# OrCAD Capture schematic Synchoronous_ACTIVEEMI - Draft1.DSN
size Custom
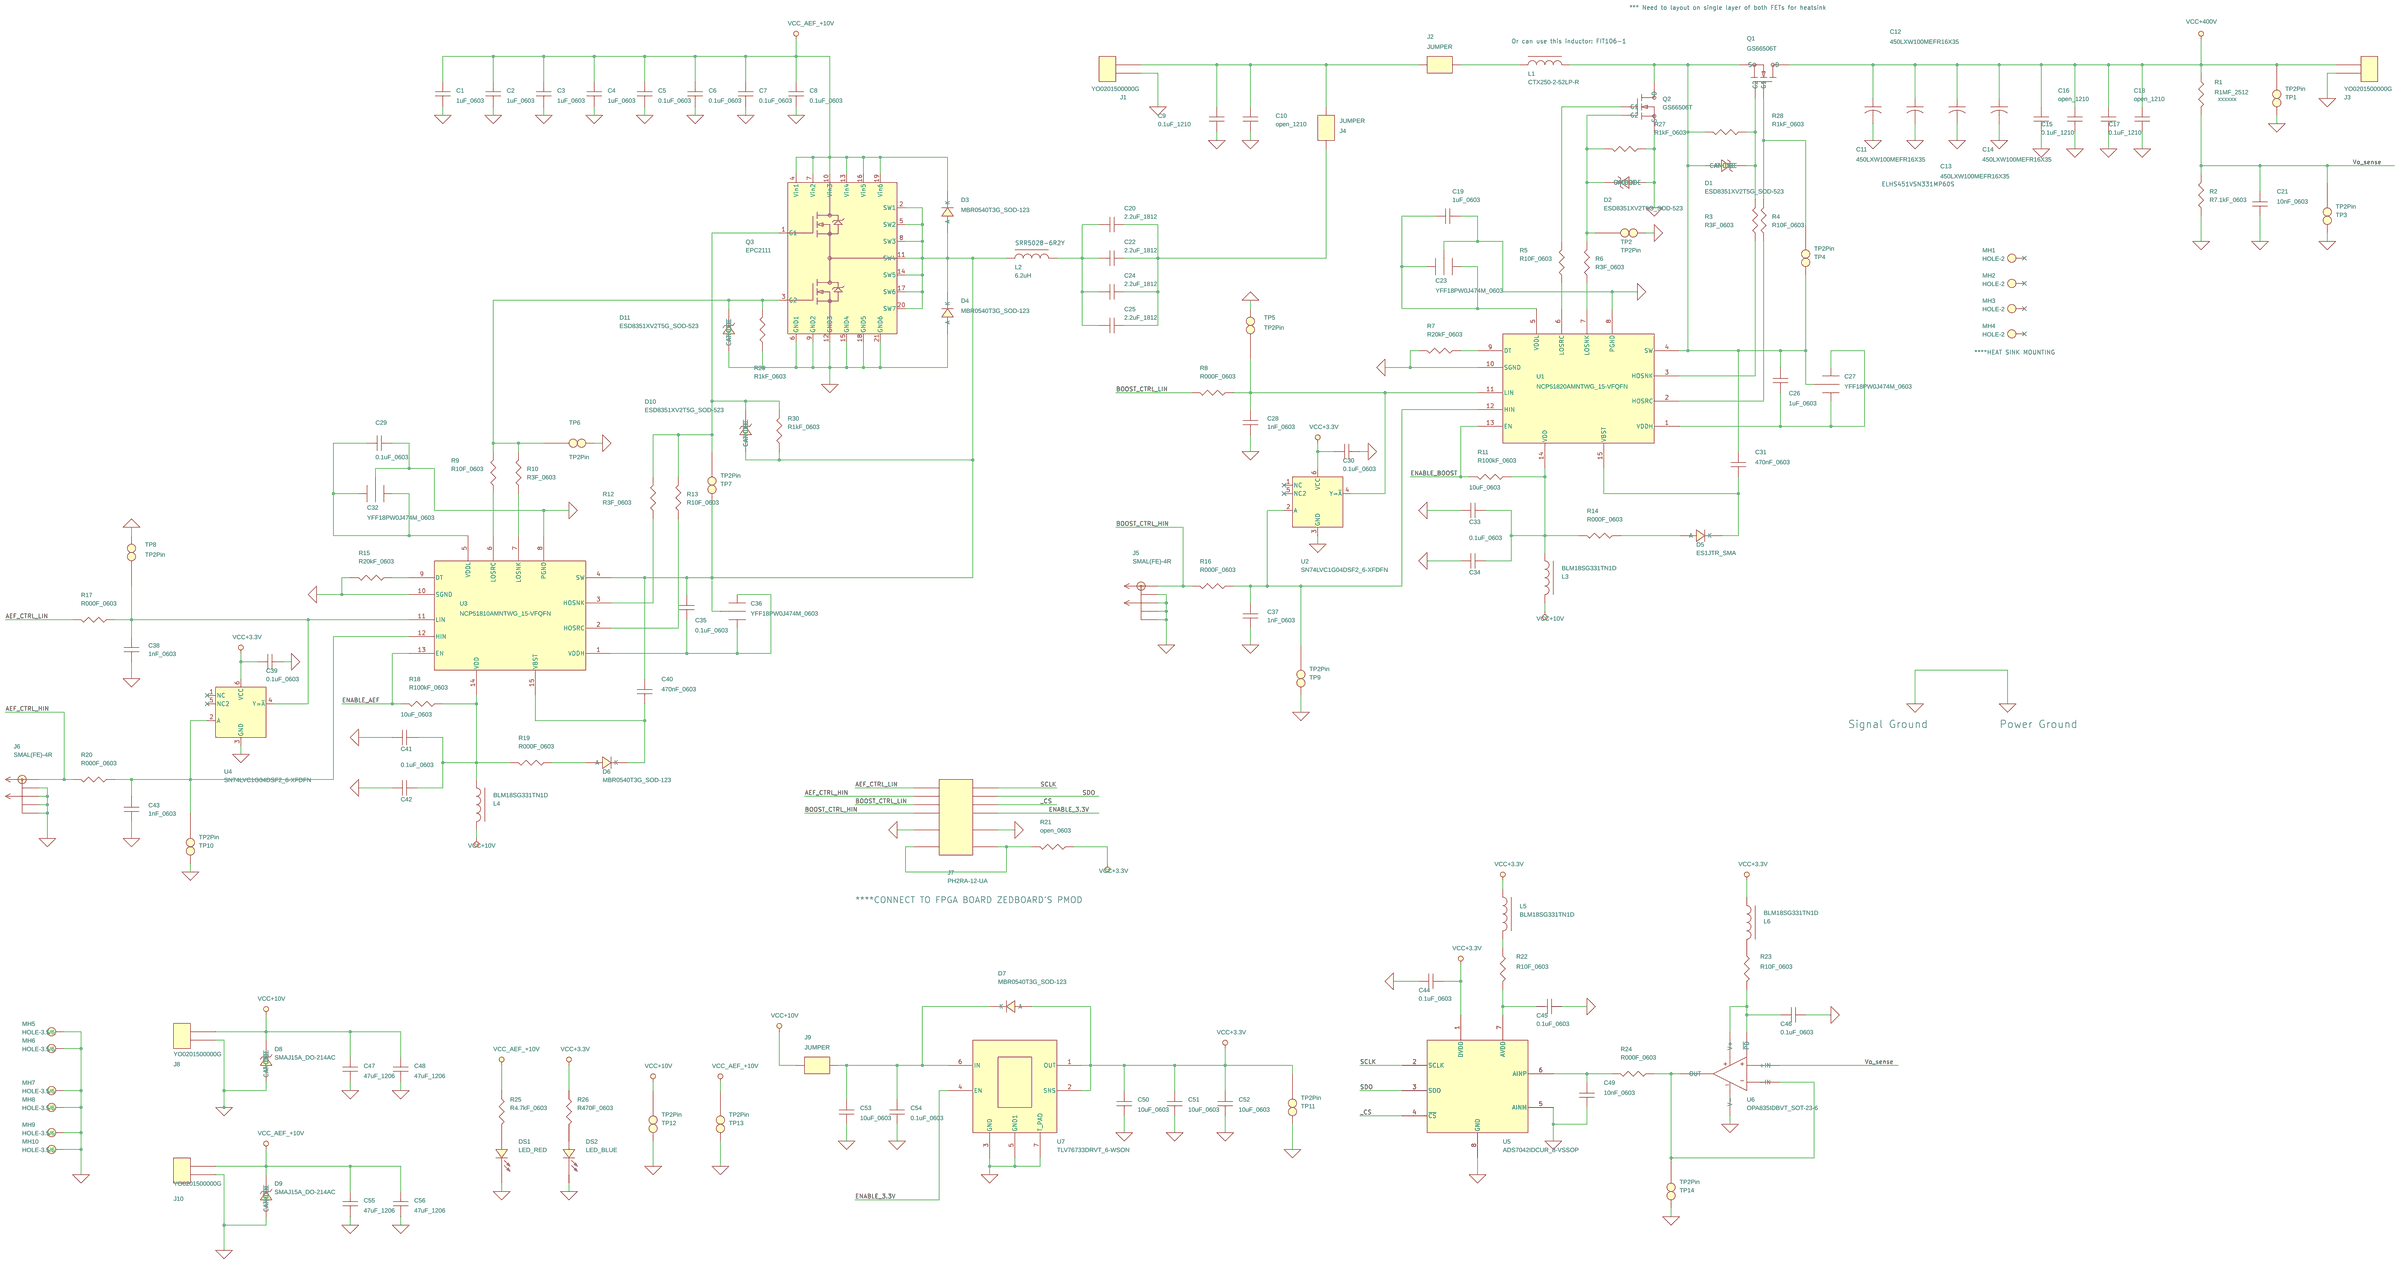
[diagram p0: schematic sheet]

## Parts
C1  1uF_0603  [OPEN_1206]
C2  1uF_0603  [OPEN_1206]
C3  1uF_0603  [OPEN_1206]
C4  1uF_0603  [OPEN_1206]
C5  0.1uF_0603  [OPEN_1206]
C6  0.1uF_0603  [OPEN_1206]
C7  0.1uF_0603  [OPEN_1206]
C8  0.1uF_0603  [OPEN_1206]
C9  0.1uF_1210  [ROC_CAP_021]
C10  open_1210  [ROC_CAP_021]
C11  450LXW100MEFR16X35  [ELHS451VSN331MP60S]
C12  450LXW100MEFR16X35  [ELHS451VSN331MP60S]
C13  450LXW100MEFR16X35  [ELHS451VSN331MP60S]
C14  450LXW100MEFR16X35  [ELHS451VSN331MP60S]
C15  0.1uF_1210  [22UF_1210]
C16  open_1210  [22UF_1210]
C17  0.1uF_1210  [22UF_1210]
C18  open_1210  [22UF_1210]
C19  1uF_0603  [C1608]
C20  2.2uF_1812  [C1608]
C21  10nF_0603  [C1608]
C22  2.2uF_1812  [C1608]
C23  YFF18PW0J474M_0603  [FEEDTHRU_0603]
C24  2.2uF_1812  [C1608]
C25  2.2uF_1812  [C1608]
C26  1uF_0603  [C1608]
C27  YFF18PW0J474M_0603  [FEEDTHRU_0603]
C28  1nF_0603  [C1608]
C29  0.1uF_0603  [C1608]
C30  0.1uF_0603  [C1608]
C31  470nF_0603  [C1608]
C32  YFF18PW0J474M_0603  [FEEDTHRU_0603]
C33  10uF_0603  [C1608]
C34  0.1uF_0603  [C1608]
C35  0.1uF_0603  [C1608]
C36  YFF18PW0J474M_0603  [FEEDTHRU_0603]
C37  1nF_0603  [C1608]
C38  1nF_0603  [C1608]
C39  0.1uF_0603  [C1608]
C40  470nF_0603  [C1608]
C41  10uF_0603  [C1608]
C42  0.1uF_0603  [C1608]
C43  1nF_0603  [C1608]
C44  0.1uF_0603  [C1608]
C45  0.1uF_0603  [C1608]
C46  0.1uF_0603  [C1608]
C47  47uF_1206  [OPEN_1206]
C48  47uF_1206  [OPEN_1206]
C49  10nF_0603  [C1608]
C50  10uF_0603  [C1608]
C51  10uF_0603  [C1608]
C52  10uF_0603  [C1608]
C53  10uF_0603  [C1608]
C54  0.1uF_0603  [C1608]
C55  47uF_1206  [OPEN_1206]
C56  47uF_1206  [OPEN_1206]
D1  ESD8351XV2T5G_SOD-523  [SMAJ22A_DO-214AC]
D2  ESD8351XV2T5G_SOD-523  [SMAJ22A_DO-214AC]
D3  MBR0540T3G_SOD-123  [MBR0540T3G_SOD-123]
D4  MBR0540T3G_SOD-123  [MBR0540T3G_SOD-123]
D5  ES1JTR_SMA  [MBR0540T3G_SOD-123]
D6  MBR0540T3G_SOD-123  [MBR0540T3G_SOD-123]
D7  MBR0540T3G_SOD-123  [MBR0540T3G_SOD-123]
D8  SMAJ15A_DO-214AC  [SMAJ6.0CA_DO-214AC]
D9  SMAJ15A_DO-214AC  [SMAJ6.0CA_DO-214AC]
D10  ESD8351XV2T5G_SOD-523  [SMAJ22A_DO-214AC]
D11  ESD8351XV2T5G_SOD-523  [SMAJ22A_DO-214AC]
DS1  LED_RED  [598-8170-107F]
DS2  LED_BLUE  [598-8170-107F]
J1  YO0201500000G  [ED120/2DS]
J2  JUMPER  [ED120/2DS]
J3  YO0201500000G  [ED120/2DS]
J4  JUMPER  [ED120/2DS]
J5  SMAL(FE)-4R  [SMBL(FE)-4R]
J6  SMAL(FE)-4R  [SMBL(FE)-4R]
J7  PH2RA-12-UA
J8  YO0201500000G  [ED120/2DS]
J9  JUMPER  [ED120/2DS]
J10  YO0201500000G  [ED120/2DS]
L1  CTX250-2-52LP-R  [CTX250-2-52LP-R]
L2  6.2uH  [CTX250-2-52LP-R]
L3  BLM18SG331TN1D  [L1608]
L4  BLM18SG331TN1D  [L1608]
L5  BLM18SG331TN1D  [L1608]
L6  BLM18SG331TN1D  [L1608]
MH1  HOLE-2  [HOLE-3.2/6]
MH2  HOLE-2  [HOLE-3.2/6]
MH3  HOLE-2  [HOLE-3.2/6]
MH4  HOLE-2  [HOLE-3.2/6]
MH5  HOLE-3.5/6  [HOLE-3.2/6]
MH6  HOLE-3.5/6  [HOLE-3.2/6]
MH7  HOLE-3.5/6  [HOLE-3.2/6]
MH8  HOLE-3.5/6  [HOLE-3.2/6]
MH9  HOLE-3.5/6  [HOLE-3.2/6]
MH10  HOLE-3.5/6  [HOLE-3.2/6]
Q1  GS66506T  [FCP165N65S3_WHEATSINK]
Q2  GS66506T  [FCP165N65S3_WHEATSINK]
Q3  EPC2111  [EPC8004/DIE]
R1  R1MF_2512  [R_2512]
R2  R7.1kF_0603  [R_1608]
R3  R3F_0603  [R_1608]
R4  R10F_0603  [R_1608]
R5  R10F_0603  [R_1608]
R6  R3F_0603  [R_1608]
R7  R20kF_0603  [R_1608]
R8  R000F_0603  [R_1608]
R9  R10F_0603  [R_1608]
R10  R3F_0603  [R_1608]
R11  R100kF_0603  [R_1608]
R12  R3F_0603  [R_1608]
R13  R10F_0603  [R_1608]
R14  R000F_0603  [R_1608]
R15  R20kF_0603  [R_1608]
R16  R000F_0603  [R_1608]
R17  R000F_0603  [R_1608]
R18  R100kF_0603  [R_1608]
R19  R000F_0603  [R_1608]
R20  R000F_0603  [R_1608]
R21  open_0603  [R_1608]
R22  R10F_0603  [R_1608]
R23  R10F_0603  [R_1608]
R24  R000F_0603  [R_1608]
R25  R4.7kF_0603  [R_1608]
R26  R470F_0603  [R_1608]
R27  R1kF_0603  [R_1608]
R28  R1kF_0603  [R_1608]
R29  R1kF_0603  [R_1608]
R30  R1kF_0603  [R_1608]
TP1  TP2Pin  [TP2PIN]
TP2  TP2Pin  [TP2PIN]
TP3  TP2Pin  [TP2PIN]
TP4  TP2Pin  [TP2PIN]
TP5  TP2Pin  [TP2PIN]
TP6  TP2Pin  [TP2PIN]
TP7  TP2Pin  [TP2PIN]
TP8  TP2Pin  [TP2PIN]
TP9  TP2Pin  [TP2PIN]
TP10  TP2Pin  [TP2PIN]
TP11  TP2Pin  [TP2PIN]
TP12  TP2Pin  [TP2PIN]
TP13  TP2Pin  [TP2PIN]
TP14  TP2Pin  [TP2PIN]
U1  NCP51820AMNTWG_15-VFQFN  [L21723]
U2  SN74LVC1G04DSF2_6-XFDFN
U3  NCP51810AMNTWG_15-VFQFN  [L21723]
U4  SN74LVC1G04DSF2_6-XFDFN
U5  ADS7042IDCUR_8-VSSOP
U6  OPA835IDBVT_SOT-23-6  [DJN_IC_8-SOIC]
U7  TLV76733DRVT_6-WSON

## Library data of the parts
C1-C8 C47 C48 C55 C56 = CAP_NP_1: PART NO: 151273
C9 C10 C15-C22 C24-C26 C28-C31 C33-C35 C37-C46 C49-C54 = CAP_NP_1
C11-C14 = CAP_0
C23 C27 C32 C36 = CAP_NP_0
D1 D2 D10 D11 = DIODE_ZENER_0: PART NO: 40002129
D3-D7 = DIODE_5: PART NO: 40001919
D8 D9 = DIODE_ZENER_0
DS1 DS2 = LED_0
J1 J3 J8 J10 = CON2
J2 J4 J9 = CON2_1
J5 J6 = 142-0701-506_0
J7 = CON12A_0
L1 L2 = INDUCTOR_4
L3-L6 = CHOKE_1
MH1-MH10 = T_POINT_R
Q1 Q2 = IRFZ24N_TO_5: PART NO: 1063683; PATH NO: 1063683
Q3 = IRFZ24N_TO_8: PATH NO: 1063683
R1 = RESISTOR_0: PART NO: xxxxxx
R2-R24 R27-R30 = R_0
R25 R26 = RESISTOR
TP1-TP14 = T_POINT_R_1
U1 U3 = CON8A_4
U2 U4 = CON6A_0
U5 = CON8A_5
U6 = OPA658_SOT_1
U7 = CON8A_6

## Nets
GND_POWER: C1.2 C2.2 C3.2 C4.2 C5.2 C6.2 C7.2 C8.2 C9.2 C10.2 C11.2 C12.2 C13.2 C14.2 C15.2 C16.2 C17.2 C18.2 C19.2 C21.1 C23.3 C28.1 C29.2 C30.2 C32.3 C33.1 C34.1 C37.1 C38.1 C39.2 C41.1 C42.1 C43.1 C44.1 C45.1 C46.1 C47.2 C48.2 C49.1 C50.1 C51.1 C52.1 C53.1 C54.1 C55.2 C56.2 D2.1(ANODE) D4.1(A) D8.1(ANODE) D9.1(ANODE) D11.1(ANODE) DS1.1(CATHODE) DS2.1(CATHODE) J1.1 J3.1 J5.2 J5.3 J5.4 J5.5 J6.2 J6.3 J6.4 J6.5 J7.9 J7.10 J8.1 J10.1 MH5.1(TP) MH6.1(TP) MH7.1(TP) MH8.1(TP) MH9.1(TP) MH10.1(TP) Q2.3(S) Q3.6(GND1) Q3.9(GND2) Q3.12(GND3) Q3.15(GND4) Q3.18(GND5) Q3.21(GND6) R2.2 R7.1 R15.1 R27.2 R29.2 TP1.2(GND) TP2.2(GND) TP3.2(GND) TP5.2(GND) TP6.2(GND) TP8.2(GND) TP9.2(GND) TP10.2(GND) TP11.2(GND) TP12.2(GND) TP13.2(GND) TP14.2(GND) U1.8(PGND) U1.10(SGND) U2.3(GND) U3.8(PGND) U3.10(SGND) U4.3(GND) U5.5(AINM) U5.8(GND) U6.2(V-) U7.3(GND) U7.5(GND1) U7.7(T_PAD)
Vcc+3.3V: C30.1 C39.1 C44.2 C50.2 C51.2 C52.2 D7.1(A) L5.2 L6.2 R21.2 R26.1 TP11.1(TP) U2.6(VCC) U4.6(VCC) U5.1(DVDD) U7.1(OUT) U7.2(SNS)
Vcc+10V: C47.1 C48.1 D8.2(CATHODE) J8.2 J9.1 L3.1 L4.1 TP12.1(TP)
Vcc+400V: C11.1 C12.1 C13.1 C14.1 C15.1 C16.1 C17.1 C18.1 J3.2 Q1.1(D) R1.1 TP1.1(TP)
Vcc_AEF_+10V: C1.1 C2.1 C3.1 C4.1 C5.1 C6.1 C7.1 C8.1 C55.1 C56.1 D3.2(K) D9.2(CATHODE) J10.2 Q3.4(Vin1) Q3.7(Vin2) Q3.10(Vin3) Q3.13(Vin4) Q3.16(Vin5) Q3.19(Vin6) R25.1 TP13.1(TP)
_CS: J7.6 U5.4(~{CS})
AEF_CTRL_HIN: J6.1 J7.3 R20.1
AEF_CTRL_LIN: J7.1 R17.1
BOOST_CTRL_HIN: J5.1 J7.7 R16.1
BOOST_CTRL_LIN: J7.5 R8.1
ENABLE_3.3V: J7.8 U7.4(EN)
ENABLE_AEF: R18.1 U3.13(EN)
ENABLE_BOOST: R11.1 U1.13(EN)
SCLK: J7.2 U5.2(SCLK)
SDO: J7.4 U5.3(SDO)
Vo_sense: C21.2 R1.2 R2.1 TP3.1(TP) U6.3(+IN)
N14603984: C33.2 C34.2 L3.2 R11.2 R14.1 U1.14(VDD)
N14604370: C9.1 C10.1 J1.2 J2.1 J4.1
N14608593: C26.2 C27.3 C31.2 D1.1(ANODE) L1.2 Q1.3(S) Q2.1(D) R28.1 TP4.2(GND) U1.4(SW)
N14621888: C28.2 R8.2 TP5.1(TP) U1.11(LIN) U2.4(Y=~{A})
N14733539: D1.2(CATHODE) Q1.4(G2) R3.1 R28.2
N14733575: Q1.2(G1) R4.1 TP4.1(TP)
N14733579: R3.2 U1.3(HOSNK)
N14733586: R4.2 U1.2(HOSRC)
N14733638: C26.1 C27.1 C27.2 U1.1(VDDH)
N14737089: Q2.2(G1) R5.1
N14737096: D2.2(CATHODE) Q2.4(G2) R6.1 R27.1 TP2.1(TP)
N14737145: R6.2 U1.7(LOSNK)
N14737193: R5.2 U1.6(LOSRC)
N14740178: C19.1 C23.1 C23.2 U1.5(VDDL)
N14741139: C31.1 D5.2(K) U1.15(VBST)
N14748206: R7.2 U1.9(DT)
N14756321: C37.2 R16.2 TP9.1(TP) U1.12(HIN) U2.2(A)
N14763076: D5.1(A) R14.2
N14791796: D11.2(CATHODE) Q3.3(G2) R9.1 R10.1 R29.1 TP6.1(TP)
N14791808: D10.2(CATHODE) Q3.1(G1) R12.1 R13.1 R30.1 TP7.1(TP)
N14791886: C29.1 C32.1 C32.2 U3.5(VDDL)
N14791966: R12.2 U3.3(HOSNK)
N14791970: R13.2 U3.2(HOSRC)
N14792026: R9.2 U3.6(LOSRC)
N14792030: R10.2 U3.7(LOSNK)
N14792038: C35.2 C36.3 C40.2 D3.1(A) D4.2(K) D10.1(ANODE) L2.1 Q3.2(SW1) Q3.5(SW2) Q3.8(SW3) Q3.11(SW4) Q3.14(SW5) Q3.17(SW6) Q3.20(SW7) R30.2 TP7.2(GND) U3.4(SW)
N14792154: R15.2 U3.9(DT)
N14792190: C35.1 C36.1 C36.2 U3.1(VDDH)
N14792198: C38.2 R17.2 TP8.1(TP) U3.11(LIN) U4.4(Y=~{A})
N14792348: C43.2 R20.2 TP10.1(TP) U3.12(HIN) U4.2(A)
N14792458: C41.2 C42.2 L4.2 R18.2 R19.1 U3.14(VDD)
N14792462: C40.1 D6.2(K) U3.15(VBST)
N14792694: D6.1(A) R19.2
N14800643: C20.2 C22.2 C24.2 C25.2 L2.2
N14800647: C20.1 C22.1 C24.1 C25.1 J4.2
N14802479: J2.2 L1.1
N14827932: C49.2 R24.1 U5.6(AINP)
N14828712: R24.2 TP14.1(TP) U6.1(OUT) U6.4(-IN)
N14829833: L5.1 R22.2
N14829837: C45.2 R22.1 U5.7(AVDD)
N14832157: C46.2 R23.1 U6.5(~{PD}) U6.6(V+)
N14852069: C53.2 C54.2 D7.2(K) J9.2 U7.6(IN)
N14856029: J7.11 J7.12 R21.1
N14874279: L6.1 R23.2
N14874280: DS1.2(ANODE) R25.2
N14874281: DS2.2(ANODE) R26.2

Not connected (* = marked no-connect by the designer): MH1 1(TP)*; MH2 1(TP)*; MH3 1(TP)*; MH4 1(TP)*; U2 1(NC)* 5(NC2)*; U4 1(NC)* 5(NC2)*

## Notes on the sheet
- *** Need to layout on single layer of both FETs for heatsink
- Or can use this inductor: FIT106-1
- ELHS451VSN331MP60S
- SRR5028-6R2Y
- ****HEAT SINK MOUNTING
- Signal Ground
- Power Ground
- ****CONNECT TO FPGA BOARD ZEDBOARD'S PMOD
